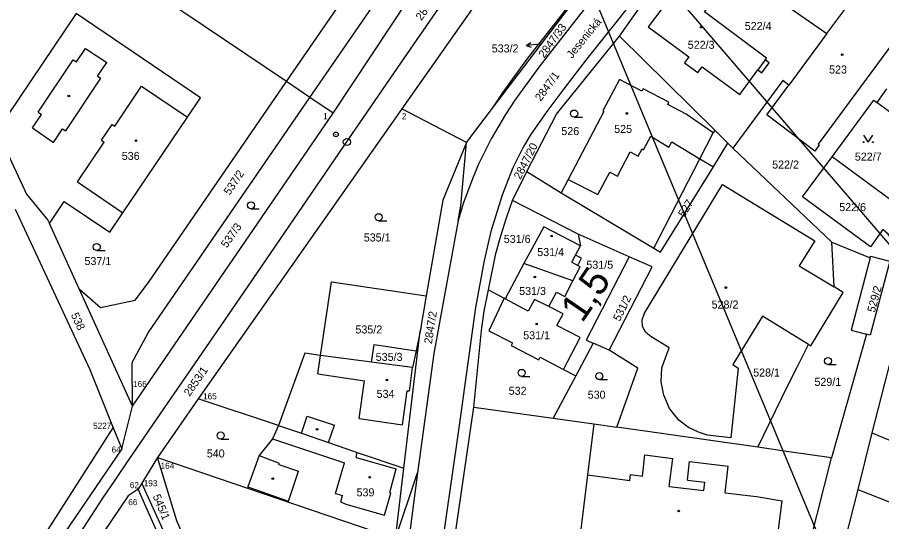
# Model space of a CAD drawing. Extents: x -558358 to -557517, y -1073785 to -1073189.
# Drawn here: x -558259.4 to -558075.9, y -1073555.9 to -1073448.9 of the extents above; entities that cross this region are included whole.
import ezdxf

# ---------------------------------------------------------------- set-up
doc = ezdxf.new("R2010")
doc.units = 0
for name, color, linetype in [('Hranice parcel', 7, 'Continuous'), ('Kolej', 7, 'Continuous'), ('Návěst místo trati', 7, 'Continuous'), ('Parcelní čísla', 7, 'Continuous'), ('Pop  PČ popisy', 7, 'Continuous'), ('Rozpiska_pole_1', 7, 'Continuous'), ('Svazek obcí údolí Desné', 7, 'Continuous'), ('Vnitřní kresba', 7, 'Continuous'), ('Vrstva 28', 7, 'Continuous'), ('Vrstva 60', 7, 'Continuous'), ('Značky budov', 7, 'Continuous'), ('Značky kultur', 7, 'Continuous')]:
    doc.layers.add(name, color=color, linetype=linetype)

msp = doc.modelspace()

# ---------------------------------------------------------------- linework, layer by layer
at = {"layer": 'Hranice parcel'}
for p, q in [((-558197.28, -1073465.89), (-558161.06, -1073413.25)), ((-558131.54, -1073452.88), (-558116.63, -1073431.7)), ((-558158.31, -1073467.84), (-558131.5, -1073432.67)), ((-558202.26, -1073462.53), (-558233.8, -1073441.26)), ((-558087.54, -1073452.3), (-558079.09, -1073440.91)), ((-558087.54, -1073452.3), (-558095.61, -1073463.24)), ((-558111.36, -1073472.82), (-558131.54, -1073452.88)), ((-558197.28, -1073465.89), (-558202.26, -1073462.53)), ((-558158.31, -1073467.84), (-558156.26, -1073464.79)), ((-558076.9, -1073466.92), (-558074.8, -1073464.07)), ((-558192.36, -1073469.21), (-558197.28, -1073465.89)), ((-558086.45, -1073478.46), (-558077.57, -1073466.44)), ((-558077.57, -1073466.44), (-558076.9, -1073466.92)), ((-558076.9, -1073466.92), (-558072.2, -1073470.34)), ((-558164.08, -1073475.42), (-558177.75, -1073468.29)), ((-558164.08, -1073475.42), (-558158.31, -1073467.84)), ((-558108.55, -1073475.6), (-558111.36, -1073472.82)), ((-558111.65, -1073480.62), (-558108.55, -1073475.6)), ((-558108.55, -1073475.6), (-558107.49, -1073476.62)), ((-558107.49, -1073476.62), (-558086.48, -1073496.61)), ((-558154.26, -1073487.77), (-558151.25, -1073481.61)), ((-558151.25, -1073481.61), (-558143.96, -1073486.09)), ((-558143.96, -1073486.09), (-558124.31, -1073497.86)), ((-558164.73, -1073488.39), (-558165.84, -1073492.01)), ((-558140.32, -1073494.88), (-558154.26, -1073487.77)), ((-558246.29, -1073506.44), (-558252.58, -1073492.61)), ((-558140.32, -1073494.88), (-558139.88, -1073497.35)), ((-558129.53, -1073499.66), (-558140.32, -1073494.88)), ((-558085.97, -1073506.08), (-558086.48, -1073496.61)), ((-558086.48, -1073496.61), (-558078.35, -1073499.89)), ((-558078.35, -1073499.89), (-558078.27, -1073499.57)), ((-558078.27, -1073499.57), (-558074.22, -1073500.6)), ((-558151.86, -1073501.13), (-558155.87, -1073508.56)), ((-558141.49, -1073504.81), (-558151.86, -1073501.13)), ((-558074.22, -1073500.6), (-558078.34, -1073516.28)), ((-558234.96, -1073531.36), (-558246.29, -1073506.44)), ((-558159.39, -1073506.66), (-558156.05, -1073508.46)), ((-558172.6, -1073507.93), (-558173.92, -1073515.47)), ((-558155.87, -1073508.56), (-558156.05, -1073508.46)), ((-558072, -1073513.63), (-558078.01, -1073537.04)), ((-558177.37, -1073544.49), (-558173.92, -1073515.47)), ((-558173.92, -1073515.47), (-558174.76, -1073519.59)), ((-558079.12, -1073516.08), (-558086.54, -1073542.34)), ((-558078.34, -1073516.28), (-558079.12, -1073516.08)), ((-558137.14, -1073518.03), (-558140.85, -1073524.92)), ((-558133.75, -1073519.51), (-558137.14, -1073518.03)), ((-558234.96, -1073531.36), (-558235.03, -1073522.1)), ((-558184.24, -1073522.04), (-558195.03, -1073520.62)), ((-558143.44, -1073523.57), (-558140.85, -1073524.92)), ((-558140.85, -1073524.92), (-558145.69, -1073533.93)), ((-558203.93, -1073535.45), (-558220.99, -1073529.81)), ((-558162.5, -1073531.6), (-558145.69, -1073533.93)), ((-558145.69, -1073533.93), (-558137.04, -1073535.13)), ((-558137.04, -1073535.13), (-558132.14, -1073535.81)), ((-558102.24, -1073540.03), (-558132.14, -1073535.81)), ((-558078.01, -1073537.04), (-558080.96, -1073549.01)), ((-558078.01, -1073537.04), (-558050.57, -1073548.21)), ((-558229.66, -1073542.22), (-558210.55, -1073548.74)), ((-558179.14, -1073559.41), (-558177.37, -1073544.49)), ((-558179.14, -1073559.41), (-558174.43, -1073545.49)), ((-558174.43, -1073545.49), (-558176.44, -1073560.75)), ((-558218.9, -1073578.68), (-558232.98, -1073547.69)), ((-558220.27, -1073579.28), (-558233.76, -1073548.97)), ((-558210.55, -1073548.74), (-558179.99, -1073559.12)), ((-558080.96, -1073549.01), (-558086.83, -1073571.83)), ((-558080.96, -1073549.01), (-558055.56, -1073559.09))]:
    msp.add_line(p, q, dxfattribs=at)
for points in [[(-558086.19, -1073392.25), (-558100.56, -1073410.01), (-558117.51, -1073431.08), (-558131.78, -1073449.27), (-558138.48, -1073457.68), (-558143.38, -1073464.02), (-558146.99, -1073468.89), (-558150.46, -1073473.83), (-558152.02, -1073476.41), (-558154.26, -1073480.97), (-558156.46, -1073486.6), (-558158.91, -1073494.31), (-558160.3, -1073500.48), (-558162.16, -1073510.4), (-558165.76, -1073536.46), (-558169.94, -1073565.43), (-558173.74, -1073591.61), (-558177.66, -1073620.33), (-558178.51, -1073631.87), (-558179.02, -1073643), (-558179.24, -1073655.12), (-558179.45, -1073666.94), (-558179.49, -1073675.4)], [(-558202.26, -1073462.53), (-558188.73, -1073442.87), (-558187.31, -1073436.01), (-558191.04, -1073430.36), (-558216.02, -1073413.17)], [(-558156.26, -1073464.79), (-558151.01, -1073457.58), (-558133.63, -1073435.37), (-558133.35, -1073433.74), (-558133.31, -1073429.98), (-558133.56, -1073429.34)], [(-558129.07, -1073430.81), (-558128.89, -1073431.83), (-558128.89, -1073432.84), (-558129.1, -1073433.85), (-558129.56, -1073434.77), (-558130.67, -1073436.36), (-558148.52, -1073459.19), (-558153.8, -1073466.46), (-558155.8, -1073469.46), (-558158.84, -1073474.63), (-558161.5, -1073480.01), (-558162.64, -1073482.78), (-558164.73, -1073488.39)], [(-558112.83, -1073434.1), (-558108.9, -1073437.49), (-558087.54, -1073452.3)], [(-558115.24, -1073437.31), (-558125.46, -1073450.9), (-558116.85, -1073457.27), (-558117.77, -1073458.51), (-558114.97, -1073460.58), (-558114.05, -1073459.35), (-558106.05, -1073465.28), (-558102.2, -1073460.05)], [(-558100.63, -1073457.93), (-558100.36, -1073457.56), (-558113.55, -1073447.75), (-558109, -1073442.11), (-558111.2, -1073440.45), (-558110.8, -1073439.94)], [(-558252.58, -1073492.61), (-558249.44, -1073487.92), (-558239.75, -1073494.46), (-558236.97, -1073490.34), (-558223.28, -1073470.09), (-558220.49, -1073465.96), (-558246.94, -1073448.09), (-558263.73, -1073472.95)], [(-558069.01, -1073448.19), (-558089.39, -1073475.8), (-558089.17, -1073475.95), (-558090.09, -1073477.27), (-558100.29, -1073469.58), (-558095.61, -1073463.24)], [(-558151.25, -1073481.61), (-558144.94, -1073469.39), (-558131.54, -1073452.88)], [(-558102.2, -1073460.05), (-558101.38, -1073460.67), (-558099.8, -1073458.54), (-558100.63, -1073457.93)], [(-558246.29, -1073506.44), (-558241.75, -1073510.46), (-558234.37, -1073508.88), (-558231.59, -1073505.15), (-558202.26, -1073462.53)], [(-558111.36, -1073472.82), (-558111.67, -1073473.41), (-558117.43, -1073469.44), (-558121.34, -1073467.34), (-558121.11, -1073466.9), (-558126.57, -1073464.07), (-558126.8, -1073464.51), (-558131.6, -1073462.08), (-558135.08, -1073468.74), (-558134.91, -1073468.83), (-558142.45, -1073483.25), (-558143.96, -1073486.09)], [(-558095.61, -1073463.24), (-558096.89, -1073462.29), (-558107.49, -1073476.62)], [(-558235.03, -1073522.1), (-558231.61, -1073515.78), (-558197.28, -1073465.89)], [(-558263.73, -1073472.95), (-558257.48, -1073486.4), (-558252.9, -1073491.92), (-558252.58, -1073492.61)], [(-558164.08, -1073475.42), (-558169.06, -1073487.65), (-558172.6, -1073507.93)], [(-558165.84, -1073492.01), (-558165.27, -1073488.87), (-558164.08, -1073475.42)], [(-558124.31, -1073497.86), (-558114.5, -1073478.9), (-558111.65, -1073480.62)], [(-558073.57, -1073498.15), (-558073.51, -1073497.13), (-558073.7, -1073496.11), (-558074.52, -1073494.85), (-558075.64, -1073493.89), (-558078.28, -1073497.56), (-558092.71, -1073486.96), (-558086.45, -1073478.46)], [(-558070.38, -1073485.35), (-558070.76, -1073486.43), (-558071.41, -1073487.24), (-558072.33, -1073487.8), (-558073.38, -1073487.88), (-558074.36, -1073487.41), (-558086.45, -1073478.46)], [(-558124.31, -1073497.86), (-558122.86, -1073498.73), (-558111.65, -1073480.62)], [(-558091.42, -1073518.26), (-558101.25, -1073512.3), (-558107.5, -1073522.55), (-558106.36, -1073523.27), (-558107.97, -1073538.05), (-558111.12, -1073537.73), (-558112.87, -1073537.48), (-558114.81, -1073536.91), (-558116.94, -1073535.87), (-558118.99, -1073534.32), (-558120.94, -1073531.84), (-558122.18, -1073529.05), (-558122.71, -1073526.18), (-558122.56, -1073523.2), (-558121.01, -1073518.98), (-558124.91, -1073516.6), (-558126.01, -1073515.72), (-558126.67, -1073514.49), (-558126.79, -1073513.04), (-558126.28, -1073511.65), (-558109.74, -1073484.35), (-558090.14, -1073496.27), (-558093.41, -1073501.56), (-558085.97, -1073506.08)], [(-558159.39, -1073506.66), (-558157.84, -1073498.99), (-558156.78, -1073495.22), (-558155.58, -1073491.43), (-558154.26, -1073487.77)], [(-558259.89, -1073489.61), (-558244.04, -1073523.6), (-558239.03, -1073535.96)], [(-558165.84, -1073492.01), (-558171, -1073520.22), (-558174.43, -1073545.49)], [(-558139.88, -1073497.35), (-558147.64, -1073493.32), (-558151.86, -1073501.13)], [(-558141.49, -1073504.81), (-558139.95, -1073501.78), (-558140.44, -1073501.51), (-558139.64, -1073499.94), (-558140.88, -1073499.3), (-558139.88, -1073497.35)], [(-558129.53, -1073499.66), (-558138.67, -1073517.37), (-558137.14, -1073518.03)], [(-558133.75, -1073519.51), (-558124.62, -1073501.83), (-558129.53, -1073499.66)], [(-558078.35, -1073499.89), (-558082.38, -1073515.23), (-558079.12, -1073516.08)], [(-558195.03, -1073520.62), (-558192.73, -1073505.02), (-558172.6, -1073507.93)], [(-558146.56, -1073510.24), (-558144.94, -1073507.17), (-558143.16, -1073508.08), (-558141.49, -1073504.81)], [(-558162.5, -1073531.6), (-558160.9, -1073515.3), (-558160.3, -1073511.2), (-558159.39, -1073506.66)], [(-558091.42, -1073518.26), (-558090.96, -1073518.54), (-558084.08, -1073507.23), (-558085.97, -1073506.08)], [(-558156.05, -1073508.46), (-558159.29, -1073515.35), (-558154.32, -1073517.94), (-558154.58, -1073518.47), (-558148.69, -1073521.52), (-558148.41, -1073520.99), (-558143.44, -1073523.57)], [(-558146.56, -1073510.24), (-558149.62, -1073508.74), (-558150.95, -1073511.21), (-558155.87, -1073508.56)], [(-558143.44, -1073523.57), (-558139.9, -1073516.83), (-558144.85, -1073514.28), (-558143.52, -1073511.79), (-558146.56, -1073510.24)], [(-558184.24, -1073522.04), (-558183.68, -1073518.31), (-558174.76, -1073519.59)], [(-558102.24, -1073540.03), (-558095.9, -1073527.13), (-558093.83, -1073523.1), (-558091.42, -1073518.26)], [(-558195.03, -1073520.62), (-558198.39, -1073520.09), (-558203.93, -1073535.45)], [(-558174.76, -1073519.59), (-558175.5, -1073523.19), (-558184.24, -1073522.04)], [(-558132.14, -1073535.81), (-558127.68, -1073523.33), (-558133.75, -1073519.51)], [(-558169.56, -1073582.12), (-558166.59, -1073559.69), (-558162.5, -1073531.6)], [(-558203.93, -1073535.45), (-558205.25, -1073538.29), (-558208.03, -1073541.86), (-558210.44, -1073548.45), (-558210.55, -1073548.74)], [(-558203.93, -1073535.45), (-558199.11, -1073537.11), (-558193.35, -1073539.1), (-558189.69, -1073540.36), (-558187.24, -1073541.19), (-558177.37, -1073544.49)], [(-558137.04, -1073535.13), (-558138.34, -1073545.94), (-558140.1, -1073559.78), (-558127.81, -1073561.38), (-558128.13, -1073563.82), (-558128.85, -1073568.77)], [(-558086.54, -1073542.34), (-558095.62, -1073541.02), (-558102.24, -1073540.03)], [(-558219.67, -1073569.09), (-558225.55, -1073555.71), (-558229.66, -1073542.22)], [(-558099.6, -1073591.18), (-558091.09, -1073560.2), (-558086.54, -1073542.34)]]:
    msp.add_lwpolyline(points, dxfattribs=at)
at = {"layer": 'Kolej'}
for points in [[(-558222.5, -1073523.52), (-558211.35, -1073507.26), (-558189.16, -1073474.89), (-558177.86, -1073458.42), (-558166.63, -1073442.09)], [(-558246.06, -1073558.3), (-558241.22, -1073550.9), (-558238.65, -1073547.06), (-558235.71, -1073542.74), (-558232.47, -1073538.02), (-558229.71, -1073534.01), (-558222.5, -1073523.52)]]:
    msp.add_lwpolyline(points, dxfattribs=at)
at = {"layer": 'Návěst místo trati'}
msp.add_line((-558191.83, -1073473.72), (-558191.73, -1073473.72), dxfattribs=at)
for centre, radius in [((-558191.78, -1073473.72), 0.5), ((-558189.45, -1073475.32), 0.75)]:
    msp.add_circle(centre, radius, dxfattribs=at)
at = {"layer": 'Pop  PČ popisy'}
for p, q in [((-558151.36, -1073454.83), (-558150.41, -1073454.25)), ((-558148.37, -1073454.57), (-558151.36, -1073454.83)), ((-558151.36, -1073454.83), (-558150.32, -1073455.24))]:
    msp.add_line(p, q, dxfattribs=at)
at = {"layer": 'Svazek obcí údolí Desné'}
for p, q in [((-558138.47, -1073412.32), (-558177.75, -1073468.29)), ((-558192.36, -1073469.21), (-558157.08, -1073415.91)), ((-558177.75, -1073468.29), (-558220.99, -1073529.81)), ((-558234.96, -1073531.36), (-558192.36, -1073469.21)), ((-558220.99, -1073529.81), (-558229.66, -1073542.22)), ((-558220.99, -1073529.81), (-558229.66, -1073542.22)), ((-558237.23, -1073540.41), (-558234.96, -1073531.36)), ((-558239.03, -1073535.96), (-558237.23, -1073540.41)), ((-558239.03, -1073535.96), (-558237.23, -1073540.41)), ((-558229.66, -1073542.22), (-558232.98, -1073547.69)), ((-558232.98, -1073547.69), (-558233.76, -1073548.97)), ((-558232.98, -1073547.69), (-558233.76, -1073548.97))]:
    msp.add_line(p, q, dxfattribs=at)
for points in [[(-558286.79, -1073633.11), (-558279.73, -1073611.9), (-558267.63, -1073584.34), (-558254.51, -1073560.06), (-558239.03, -1073535.96)], [(-558237.23, -1073540.41), (-558250.35, -1073559.71), (-558264.4, -1073584.99), (-558277.08, -1073613.49), (-558283.33, -1073632.3), (-558290.3, -1073658.29), (-558296.01, -1073700.28), (-558297.13, -1073716.84), (-558297.21, -1073758.56)], [(-558233.76, -1073548.97), (-558235.85, -1073550.36), (-558241.19, -1073558.21), (-558248.9, -1073570.88), (-558258.93, -1073588.36)], [(-558233.76, -1073548.97), (-558235.85, -1073550.36), (-558241.19, -1073558.21), (-558248.9, -1073570.88), (-558258.93, -1073588.36)]]:
    msp.add_lwpolyline(points, dxfattribs=at)
at = {"layer": 'Vnitřní kresba'}
for p, q in [((-558246.86, -1073458.35), (-558244.94, -1073455.47)), ((-558244.94, -1073455.47), (-558240.43, -1073458.48)), ((-558254.96, -1073469.03), (-558247.53, -1073457.9)), ((-558247.53, -1073457.9), (-558246.86, -1073458.35)), ((-558242.35, -1073461.35), (-558240.43, -1073458.48)), ((-558100.63, -1073457.93), (-558102.2, -1073460.05)), ((-558242.35, -1073461.35), (-558241.66, -1073461.81)), ((-558249.13, -1073472.99), (-558241.66, -1073461.81)), ((-558238.73, -1073471.97), (-558233.06, -1073463.5)), ((-558233.06, -1073463.5), (-558223.28, -1073470.09)), ((-558256.21, -1073472.34), (-558254.3, -1073469.47)), ((-558254.96, -1073469.03), (-558254.3, -1073469.47)), ((-558256.21, -1073472.34), (-558251.73, -1073475.41)), ((-558251.73, -1073475.41), (-558249.81, -1073472.53)), ((-558249.81, -1073472.53), (-558249.13, -1073472.99)), ((-558241.52, -1073474.97), (-558239.27, -1073471.61)), ((-558239.27, -1073471.61), (-558238.73, -1073471.97)), ((-558126.45, -1073476.96), (-558124.93, -1073474.1)), ((-558124.93, -1073474.1), (-558121.12, -1073476.4)), ((-558114.5, -1073478.9), (-558111.67, -1073473.41)), ((-558246.65, -1073483.79), (-558240.98, -1073475.33)), ((-558241.52, -1073474.97), (-558240.98, -1073475.33)), ((-558121.12, -1073476.4), (-558120.46, -1073475.31)), ((-558120.46, -1073475.31), (-558114.5, -1073478.9)), ((-558132, -1073482.54), (-558129.3, -1073477.44)), ((-558129.3, -1073477.44), (-558127.63, -1073478.35)), ((-558127.63, -1073478.35), (-558126.79, -1073476.79)), ((-558126.79, -1073476.79), (-558126.45, -1073476.96)), ((-558136.15, -1073486.45), (-558133.63, -1073481.7)), ((-558133.63, -1073481.7), (-558132, -1073482.54)), ((-558142.45, -1073483.25), (-558136.15, -1073486.45)), ((-558246.65, -1073483.79), (-558236.97, -1073490.34)), ((-558141.68, -1073500.85), (-558140.88, -1073499.3)), ((-558141.68, -1073500.85), (-558140.44, -1073501.51)), ((-558195.64, -1073524.53), (-558195.03, -1073520.62)), ((-558176.08, -1073527.66), (-558175.5, -1073523.19)), ((-558195.64, -1073524.53), (-558185.73, -1073525.99)), ((-558186.85, -1073533.98), (-558185.73, -1073525.99)), ((-558177.65, -1073535.29), (-558176.63, -1073528.09)), ((-558176.63, -1073528.09), (-558176.18, -1073528.11)), ((-558176.18, -1073528.11), (-558176.08, -1073527.66)), ((-558199.11, -1073537.11), (-558197.85, -1073533.46)), ((-558197.85, -1073533.46), (-558192.08, -1073535.4)), ((-558186.85, -1073533.98), (-558177.65, -1073535.29)), ((-558193.35, -1073539.1), (-558192.08, -1073535.4)), ((-558205.25, -1073538.29), (-558189.93, -1073543.4)), ((-558208.03, -1073541.86), (-558203.81, -1073543.44)), ((-558187.49, -1073542.24), (-558187.24, -1073541.19)), ((-558187.49, -1073542.24), (-558179, -1073544.67)), ((-558126.72, -1073546.2), (-558126.22, -1073541.7)), ((-558126.22, -1073541.7), (-558120.27, -1073542.43)), ((-558203.92, -1073543.72), (-558203.81, -1073543.44)), ((-558203.92, -1073543.72), (-558199.71, -1073545.18)), ((-558191.85, -1073549.89), (-558189.93, -1073543.4)), ((-558121, -1073548.38), (-558120.27, -1073542.43)), ((-558117.17, -1073547.04), (-558116.72, -1073543.11)), ((-558116.72, -1073543.11), (-558108.48, -1073544.08)), ((-558109.12, -1073549.75), (-558108.48, -1073544.08)), ((-558201.86, -1073551.5), (-558199.71, -1073545.18)), ((-558180.35, -1073549.71), (-558179, -1073544.67)), ((-558138.34, -1073545.94), (-558129.39, -1073547.14)), ((-558129.39, -1073547.14), (-558129.22, -1073545.83)), ((-558129.22, -1073545.83), (-558126.72, -1073546.2)), ((-558117.17, -1073547.04), (-558113.48, -1073547.47)), ((-558113.69, -1073549.26), (-558113.48, -1073547.47)), ((-558210.44, -1073548.45), (-558201.86, -1073551.5)), ((-558121, -1073548.38), (-558113.69, -1073549.26)), ((-558191.85, -1073549.89), (-558190.36, -1073550.31)), ((-558190.71, -1073551.65), (-558190.36, -1073550.31)), ((-558181.43, -1073554.48), (-558180.14, -1073549.84)), ((-558180.35, -1073549.71), (-558180.14, -1073549.84)), ((-558109.12, -1073549.75), (-558102.5, -1073550.54)), ((-558102.5, -1073550.54), (-558097.04, -1073551.46)), ((-558097.85, -1073557.5), (-558097.04, -1073551.46)), ((-558190.71, -1073551.65), (-558189.68, -1073552.16)), ((-558189.68, -1073552.16), (-558181.43, -1073554.48))]:
    msp.add_line(p, q, dxfattribs=at)
at = {"layer": 'Vrstva 28'}
for p, q in [((-558150.5, -1073408.33), (-557941.76, -1073651.48)), ((-558150.16, -1073413.05), (-558044.9, -1073665.43))]:
    msp.add_line(p, q, dxfattribs=at)
at = {"layer": 'Vrstva 60'}
for p, q in [((-558177.75, -1073468.29), (-558177.75, -1073468.29)), ((-558192.36, -1073469.21), (-558192.36, -1073469.21)), ((-558220.99, -1073529.81), (-558220.99, -1073529.81)), ((-558234.96, -1073531.36), (-558234.96, -1073531.36)), ((-558239.03, -1073535.96), (-558239.03, -1073535.96)), ((-558237.23, -1073540.41), (-558237.23, -1073540.41)), ((-558229.66, -1073542.22), (-558229.66, -1073542.22)), ((-558232.98, -1073547.69), (-558232.98, -1073547.69)), ((-558233.76, -1073548.97), (-558233.76, -1073548.97)), ((-558235.85, -1073550.36), (-558235.85, -1073550.36))]:
    msp.add_line(p, q, dxfattribs=at)
at = {"layer": 'Značky budov'}
for centre in [(-558114.25, -1073450.97), (-558084.29, -1073456.8), (-558248.48, -1073465.56), (-558130.01, -1073469.27), (-558234.2, -1073475.05), (-558145.97, -1073495.27), (-558149.53, -1073503.95), (-558108.99, -1073506.2), (-558149.15, -1073513.95), (-558180.95, -1073525.8), (-558195.77, -1073536.28), (-558205.18, -1073546.74), (-558184.62, -1073546.43), (-558119.02, -1073553.6)]:
    msp.add_circle(centre, 0.175, dxfattribs=at)
at = {"layer": 'Značky kultur'}
for p, q in [((-558141.2, -1073470.05), (-558139.45, -1073470.05)), ((-558209.8, -1073489.51), (-558208.05, -1073489.51)), ((-558182.7, -1073492.04), (-558180.95, -1073492.04)), ((-558242.54, -1073498.35), (-558240.79, -1073498.35)), ((-558087.33, -1073522.53), (-558085.58, -1073522.53)), ((-558152.35, -1073525.05), (-558150.6, -1073525.05)), ((-558135.84, -1073525.74), (-558134.09, -1073525.74)), ((-558216.23, -1073538.34), (-558214.48, -1073538.34))]:
    msp.add_line(p, q, dxfattribs=at)
msp.add_lwpolyline([(-558079.77, -1073473.86), (-558078.77, -1073475.36), (-558077.77, -1073473.86)], dxfattribs=at)
for centre, radius in [((-558141.2, -1073469.3), 0.75), ((-558079.77, -1073475.36), 0.1), ((-558077.77, -1073475.36), 0.1), ((-558209.8, -1073488.76), 0.75), ((-558182.7, -1073491.29), 0.75), ((-558242.54, -1073497.6), 0.75), ((-558087.33, -1073521.78), 0.75), ((-558152.35, -1073524.3), 0.75), ((-558135.84, -1073524.99), 0.75), ((-558216.23, -1073537.59), 0.75)]:
    msp.add_circle(centre, radius, dxfattribs=at)

# ---------------------------------------------------------------- texts
at = {"layer": 'Návěst místo trati'}
msp.add_text('1,5', height=6, rotation=55.5626, dxfattribs=at).set_placement((-558139.51, -1073513.88))
at = {"layer": 'Parcelní čísla'}
for s, rotation, p in [('2847/33', 54, (-558147.56, -1073457.63)), ('2847/1', 54, (-558148.29, -1073466.81)), ('2847/20', 63, (-558152.61, -1073483.4)), ('537/2', 56, (-558214.34, -1073486.74)), ('527', 58, (-558117.82, -1073491.43)), ('537/3', 55, (-558214.94, -1073497.94)), ('529/2', 75, (-558077.38, -1073511.59)), ('531/2', 64, (-558131.51, -1073513.5)), ('538', 295, (-558248.08, -1073512)), ('2847/2', 81, (-558171.41, -1073518.24)), ('545/1', 293, (-558230.7, -1073550.47))]:
    msp.add_text(s, height=1.7, rotation=rotation, dxfattribs=at).set_placement(p)
for s, p in [('522/4', (-558104.99, -1073451.58)), ('522/3', (-558117.09, -1073455.56)), ('533/2', (-558158.7, -1073456.33)), ('523', (-558087.08, -1073460.8)), ('526', (-558143.92, -1073473.86)), ('525', (-558132.7, -1073473.41)), ('536', (-558237.23, -1073479.13)), ('522/7', (-558081.62, -1073479.28)), ('522/2', (-558099.17, -1073480.96)), ('522/6', (-558084.93, -1073489.99)), ('535/1', (-558185.86, -1073496.43)), ('531/6', (-558156.14, -1073496.74)), ('531/4', (-558149.03, -1073499.53)), ('537/1', (-558245.15, -1073501.43)), ('531/5', (-558138.61, -1073502.21)), ('531/3', (-558152.88, -1073507.78)), ('528/2', (-558112.02, -1073510.65)), ('535/2', (-558187.63, -1073515.94)), ('531/1', (-558152.01, -1073517.18)), ('535/3', (-558183.32, -1073521.76)), ('528/1', (-558103.2, -1073525.08)), ('529/1', (-558090.19, -1073527.05)), ('532', (-558155.1, -1073528.95)), ('534', (-558183.13, -1073529.6)), ('530', (-558138.32, -1073529.78)), ('540', (-558219.18, -1073542.24)), ('539', (-558187.39, -1073550.49))]:
    msp.add_text(s, height=1.7, dxfattribs=at).set_placement(p)
at = {"layer": 'Pop  PČ popisy'}
msp.add_text('Jesenická', height=1.7, rotation=51, dxfattribs=at).set_placement((-558141.65, -1073457.73))
at = {"layer": 'Rozpiska_pole_1'}
for p in [(-558173.6, -1073449.7), (-558222.82, -1073529.41)]:
    msp.add_text('2853/1', height=1.7, rotation=55, dxfattribs=at).set_placement(p)
at = {"layer": 'Vrstva 60'}
for s, p in [('1', (-558194.5, -1073470.51)), ('2', (-558177.75, -1073470.5)), ('166', (-558234.85, -1073527.32)), ('165', (-558219.97, -1073529.91)), ('5227', (-558243.31, -1073536.19)), ('64', (-558239.39, -1073541.21)), ('164', (-558228.99, -1073544.65)), ('62', (-558235.51, -1073548.76)), ('193', (-558232.57, -1073548.35)), ('66', (-558235.85, -1073552.36))]:
    msp.add_text(s, height=1.3, dxfattribs=at).set_placement(p)

doc.saveas('drawing.dxf')
